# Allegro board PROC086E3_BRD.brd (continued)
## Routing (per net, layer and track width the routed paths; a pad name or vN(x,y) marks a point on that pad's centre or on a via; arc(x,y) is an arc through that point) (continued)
CAPI2S: length 5.3
  TOP w0.178: U2.58 19.15,177.73 18.06,176.64 18.06,175.15 17.88,174.97 C24.1
CAPL12: length 3.3
  TOP w0.178: U2.4 22.58,174.69 v1(22.58,174.68) 22.58,173.73 C26.1
  BOTTOM w0.178: v1(22.58,174.68) 22.58,173.73 C26.1
CAPP12: length 3.8
  TOP w0.178: C23.1 17.56,176.75 19.04,178.23 U2.57
CAPR12: length 3.4
  TOP w0.178: U2.55 18.16,179.23 17.74,178.81 C21.1
CDCE_1V8_I2C_SCL: length 9.8
  TOP w0.178: U9.3 44.81,154.93 44.56,154.68 R68.2 44.56,153.46 43.64,152.54 39.78,152.54 v1(39.17,153.14)
  BOTTOM w0.178: U42.12 39.17,153.25 39.17,153.25 v1(39.17,153.14)
CDCE_1V8_I2C_SDA: length 12.4
  TOP w0.178: U9.4 45.46,154.9 45.72,154.65 R69.2 45.72,153.3 44.58,152.15 39.27,152.15 v1(38.28,153.14)
  BOTTOM w0.178: v1(38.28,153.14) 38.52,153.38 U42.13
CDCE_PCLK: length 21.7
  TOP w0.178: R22.2 R23.1 v1(29.01,169.17)
  BOTTOM w0.178: U42.1 36.86,160.19 36.37,159.7 33.76,159.7 33.3,160.16 33.3,164.37 32.74,164.93 28.32,164.93 27.99,165.26 27.99,168.16 v1(29.01,169.17)
CDCE_S0: length 3.4
  BOTTOM w0.178: R339.2 R342.1 37.89,161.74 38.52,161.11 U42.2
CDCE_VCTR: length 2.4
  TOP w0.178: R54.2 39.56,161.06 v1(39.82,161.32)
  BOTTOM w0.178: U42.4 v1(39.82,161.32)
CDCE_Y1: length 24.4
  TOP w0.178: R27.1 v1(28.5,167.01) ; R63.1 37.52,155.3 v1(37.31,155.51)
  L03_SIG1 w0.107: v1(37.31,155.51) 34.27,155.51 31.07,158.71 27.33,158.71 26.88,159.15 26.88,166.33 27.57,167.01 v1(28.5,167.01)
CMC_FPD_DOUT_N: length 1.5
  TOP w0.102: FL5.2 22.43,161.23 arc(22.83,161.31) C36.2
CMC_FPD_DOUT_P: length 1.5
  TOP w0.102: FL5.1 22.43,160.68 arc(22.83,160.6) C37.2
CMC_FPD_RIN_N: length 1.2
  TOP w0.102: FL3.1 15.62,181.71 arc(15.97,181.64) C17.2
CMC_FPD_RIN_P: length 1.1
  TOP w0.102: FL3.2 15.61,182.26 arc(15.96,182.33) C16.2
CMF: length 3.4
  TOP w0.178: C18.1 17.67,180.24 18.66,181.23 U2.51
CODEC1_ACLKX: length 103.5
  TOP w0.178: v1(65.51,45.96) 65.51,42.25 64.8,41.54 62.15,41.54 61.26,42.43 U32.36 ; U32.7 45.18,45.43 v1(44.68,45.93)
  L03_SIG1 w0.107: v1(44.68,45.93) 47.52,48.78 59.77,48.78 62.59,45.96 v1(65.51,45.96) 66.88,45.96 67.71,46.79 67.71,50.47 66.31,51.88 66.31,70.16 66.06,70.41 65.18,70.41 64.81,70.04 64.81,62.7 64.47,62.36 63.96,62.36 63.6,62.72 63.6,71.84 66.04,74.28 66.04,89.29 v1(65.41,89.91)
  BOTTOM w0.178: R188.2 v1(65.41,89.91)
CODEC1_I2C_ADD0: length 7.5
  TOP w0.178: U32.45 58.99,46.93 59.08,46.85 61.34,46.85 61.85,46.34 61.85,45.12 62.12,44.85 R271.1 R272.2
CODEC1_I2C_ADD1: length 8.2
  TOP w0.178: U32.44 60.99,46.43 61.39,46.03 61.39,44.03 61.74,43.68 R277.1 R278.2
CODEC1_MODE: length 3.6
  TOP w0.178: R264.2 60.62,49.58 R263.2 59.49,48.76 59.17,48.43 U32.48
CODEC1_OVF: length 5.5
  TOP w0.178: TP13.1 U32.5
CODEC1_SCKI: length 25.5
  TOP w0.178: v1(60.78,45.43) 60.28,44.93 U32.41
  BOTTOM w0.178: v1(60.78,45.43) 60.78,46.86 64.58,50.66 64.58,64.12 63.95,64.74 R215.2
CODEC1_VREFAD1: length 12.5
  TOP w0.254: C157.1 45.19,57.01 45.77,56.42 50.37,56.42 51.09,55.7 U32.59
CODEC1_VREFAD2: length 11.5
  TOP w0.254: C161.1 44.54,55.38 45.34,55.38 45.8,55.84 50.09,55.84 50.59,55.33 U32.60
CODEC1_ZERO: length 5.7
  TOP w0.178: TP14.1 41.89,42.43 U32.13
CODEC2_ACLKX: length 44.4
  TOP w0.178: U19.36 v1(45.51,109.39) ; U19.7 v1(59.17,106.39)
  L03_SIG1 w0.107: v1(65.41,98.82) 64.59,99.64 64.59,102.42 63.81,103.2 56.85,103.2 56.61,103.44 56.61,104.15 56.88,104.42 60.72,104.42 60.89,104.6 60.89,104.97 60.59,105.27 56.3,105.27 56.16,105.41 56.16,105.98 56.32,106.13 58.92,106.13 v1(59.17,106.39)
  BOTTOM w0.178: v1(59.17,106.39) 48.51,106.39 v1(45.51,109.39) ; R187.2 v1(65.41,98.82)
CODEC2_I2C_ADD0: length 5.5
  TOP w0.178: U19.45 46.62,104.91 44.3,104.91 43.32,105.89 R167.1 R166.2
CODEC2_I2C_ADD1: length 6.1
  TOP w0.178: U19.44 44.38,105.39 43.64,106.13 43.64,106.76 43.32,107.08 R159.1 R158.2
CODEC2_MODE: length 3.3
  TOP w0.178: R174.2 44.55,102.27 R171.2 U19.48
CODEC2_OVF: length 11.2
  TOP w0.178: v1(68.4,105.78) 67.68,105.06 62.28,105.06 61.52,105.82 60.91,105.82 60.47,105.39 U19.5
CODEC2_SCKI: length 56.3
  TOP w0.178: v1(44.24,107.39) 44.74,106.89 U19.41
  L03_SIG1 w0.107: v1(63.95,74.31) 64.9,75.26 64.9,96.95 66.27,98.32 66.27,101.69 61.09,106.87 58.5,106.87 58.19,106.56 47.14,106.56 46.82,106.89 44.74,106.89 v1(44.24,107.39)
  BOTTOM w0.178: R214.2 v1(63.95,74.31)
CODEC2_VREFAD1: length 8.3
  TOP w0.254: C312.1 51.76,94.62 53.59,96.45 U19.59
CODEC2_VREFAD2: length 7.8
  TOP w0.254: U19.60 54.09,95.73 53.51,95.15 C311.1
CODEC2_ZERO: length 11.2
  TOP w0.178: v1(68.4,111.35) 66.79,109.74 65.28,109.74 64.93,109.39 U19.13
CODEC_RESETN: length 129
  TOP w0.178: U32.4 v1(44.68,46.93) ; v1(61.29,105.27) 60.91,104.89 U19.4 ; U15.1 v1(61.28,133.67)
  L03_SIG1 w0.107: v1(61.29,105.27) 62.2,105.27 65.91,101.56 65.91,98.62 63.88,96.59 63.88,76.12 61.28,73.52 61.28,62.39 55,56.12 41.53,56.12 40.36,54.95 40.36,47.43 40.86,46.93 v1(44.68,46.93)
  L08_SIG2 w0.107: v1(61.29,105.27) 61.3,105.26 64.74,105.26 65.3,105.82 65.3,106.89 70.36,111.95 70.36,119.92 62,128.28 62,132.95 v1(61.28,133.67)
  BOTTOM w0.178: R498.1 v1(44.68,46.93)
CODEC_SCKI: length 51.9
  TOP w0.178: J2.16 v1(93.68,48.63)
  L03_SIG1 w0.107: v1(74.7,70.47) 74.7,48.01 75.05,47.66 92.71,47.66 v1(93.68,48.63)
  BOTTOM w0.178: R538.1 74.68,70.46 v1(74.7,70.47)
CODECA_LIN_L: length 5.7
  BOTTOM w0.381: C332.2 9.86,78.92 J15.5B
CODECA_LIN_L_AC: length 1.1
  BOTTOM w0.381: C332.1 R449.1
CODECA_LIN_R: length 18.5
  BOTTOM w0.381: C134.2 23.82,69.29 22.96,68.44 15.82,68.44 13.39,70.87 9.05,70.87 J15.2B
CODECA_LIN_R_AC: length 1.7
  BOTTOM w0.381: C134.1 R210.1
CODECA_MIC1_L: length 33.2
  TOP w0.381: R227.1 26.26,64.45 23.42,67.29 10.28,67.29 8.48,65.49 J16.5B 8.48,59.45 9.49,58.44 R232.1
CODECA_MIC1_R: length 25.3
  TOP w0.381: R245.1 26.26,50.8 25.99,50.53 16.13,50.53 14.31,52.35 R237.1 9.36,56.46 8.48,55.58 J16.2B
CODECA_MIC2_L: length 23.5
  BOTTOM w0.381: R470.1 11.77,56.46 10.98,55.67 J16.5A 13.19,50.52 25.99,50.52 26.26,50.78 R478.1
CODECA_MIC2_R: length 26.5
  BOTTOM w0.381: R460.1 26.26,64.48 25.52,65.22 J16.2A 10.98,59.23 11.78,58.44 R467.1
CODECA_VOUT1: length 7.9
  BOTTOM w0.381: C373.2 R520.1 11.44,28.35 J19.5B
CODECA_VOUT2: length 7.9
  BOTTOM w0.381: C380.2 R522.1 11.44,24.26 J19.2B
CODECA_VOUT3: length 8
  TOP w0.381: C204.2 R300.1 11.65,24.26 10.98,23.59 J19.5A
CODECA_VOUT4: length 8.1
  TOP w0.381: C196.2 R296.1 11.46,28.35 10.98,28.83 J19.2A
CODECA_VOUT5: length 8
  BOTTOM w0.381: C359.2 R497.1 11.51,44.6 J18.5B
CODECA_VOUT6: length 8
  BOTTOM w0.381: J18.2B 11.51,40.67 R500.1 C366.2
CODECA_VOUT7: length 8.1
  TOP w0.381: J18.5A 10.98,39.84 11.81,40.67 R269.1 C183.2
CODECA_VOUT8: length 8
  TOP w0.381: J18.2A 10.98,45.54 11.92,44.6 R266.1 C168.2
CODECB_LIN_L: length 9.8
  TOP w0.381: C338.2 11.74,76.62 10.98,75.86 J15.5A
CODECB_LIN_L_AC: length 2.4
  TOP w0.381: C338.1 R457.1
CODECB_LIN_R: length 2.3
  BOTTOM w0.381: C122.2 J15.2A
CODECB_LIN_R_AC: length 16.9
  TOP w0.381: R200.1 v1(25.59,76.52)
  BOTTOM w0.381: v1(25.59,76.52) 25.59,80.79 24.83,81.56 C122.1
CODECB_MIC1_L: length 28.3
  TOP w0.381: J13.5B 8.48,92.21 9.33,91.36 R185.1 14.31,95.57 16.26,97.52 25.7,97.52 26.16,97.07 R178.1
CODECB_MIC1_R: length 24.9
  TOP w0.381: R197.1 26.16,84.14 25.82,83.8 16.26,83.8 14.31,85.75 R190.1 9.45,89.38 8.48,88.41 J13.2B
CODECB_MIC2_L: length 23.7
  BOTTOM w0.381: R436.1 26.16,84.13 25.83,83.8 16.26,83.8 14.31,85.75 R430.1 11.87,89.38 10.98,88.5 J13.5A
CODECB_MIC2_R: length 27.1
  BOTTOM w0.381: R419.1 26.16,97.11 25.75,97.52 16.26,97.52 14.31,95.57 R427.1 11.81,91.36 10.98,92.19 J13.2A
CODECB_VOUT1: length 8.1
  BOTTOM w0.381: J12.5B 11.74,109.72 R404.1 C293.2
CODECB_VOUT2: length 8
  BOTTOM w0.381: J12.2B 11.28,105.78 R406.1 C301.2
CODECB_VOUT3: length 7.9
  TOP w0.381: C89.2 R155.1 11.69,105.78 10.98,105.07 J12.5A
CODECB_VOUT4: length 8.4
  TOP w0.381: J12.2A 10.98,110.35 11.61,109.72 R151.1 C72.2
CODECB_VOUT5: length 8
  BOTTOM w0.381: J11.5B 11.51,126.28 R380.1 C279.2
CODECB_VOUT6: length 8
  BOTTOM w0.381: J11.2B 11.51,122.35 R382.1 C286.2
CODECB_VOUT7: length 8.3
  TOP w0.381: J11.5A 10.98,121.9 11.43,122.35 R128.1 C64.2
CODECB_VOUT8: length 8.3
  TOP w0.381: C52.2 R118.1 11.48,126.28 10.98,126.79 J11.2A
CON_UB921_INTB: length 72.6
  TOP w0.178: J1.87 83.01,121.01 v1(82.51,121.51) ; R65.2 v1(33.2,153.42)
  L08_SIG2 w0.107: v1(75.87,121.51) 73.15,124.23 73.15,126.96 70.76,129.35 68.43,129.35 67.16,130.62 67.16,133.05 63.57,136.64 61.37,136.64 60.43,137.58 55.65,137.58 54.69,136.62 52.02,136.62 49.54,139.1 48.25,139.1 45.15,142.2 45.15,146.88 39.88,152.15 34.46,152.15 v1(33.2,153.42)
  BOTTOM w0.178: v1(75.87,121.51) v1(82.51,121.51)
CON_VPFE0_DATA6: length 63.8
  TOP w0.178: U10.13 61.21,139.1 61.49,138.82 62.2,138.82 62.23,138.79 63.5,138.79 64.34,137.96 v1(64.34,137.14) ; J1.22 v1(92.41,99.51)
  L03_SIG1 w0.107: v1(92.41,99.51) 93.25,100.35 93.25,105.75 90.73,108.26 90.73,113.9 83.62,121.01 81.84,121.01 78.28,124.57 78.28,129.8 77.83,130.26 76,130.26 75.89,130.37 75.89,131.01 75.78,131.11 75.57,131.11 75.46,131.01 75.46,130.37 75.36,130.26 70.51,130.26 64.87,135.9 64.87,136.61 v1(64.34,137.14)
CON_VPFE0_DATA7: length 63.6
  TOP w0.178: U10.15 62.21,139.4 62.41,139.2 63.65,139.2 64.85,138.01 64.85,136.66 v1(65.38,136.13) ; J1.24 v1(93.78,100.01)
  L03_SIG1 w0.107: v1(65.38,136.13) 65.38,135.9 67.72,133.56 72.56,133.56 73.33,132.79 78.75,132.79 79.44,132.1 79.44,124.78 82.04,122.18 83.06,122.18 91.14,114.11 91.14,108.57 93.57,106.13 93.57,100.21 v1(93.78,100.01)
CON_VPFE0_DATA11: length 63.6
  TOP w0.178: v1(65.38,137.14) 65.53,137.3 65.53,137.88 63.71,139.7 U10.18 ; J1.56 v1(92.41,108.01)
  L03_SIG1 w0.107: v1(65.38,137.14) 65.9,136.62 65.9,135.83 67.85,133.89 72.67,133.89 73.46,133.1 79.05,133.1 80.52,131.63 80.52,124.32 82.32,122.51 83.76,122.51 84.32,123.07 88.52,123.07 88.82,122.77 89.47,122.77 89.56,122.68 89.56,122.55 89.47,122.45 88.82,122.45 88.72,122.36 88.72,122.23 88.82,122.13 89.47,122.13 89.56,122.04 89.56,121.91 89.47,121.81 88.82,121.81 88.72,121.72 88.72,121.59 88.82,121.49 89.47,121.49 89.56,121.4 89.56,121.27 89.47,121.17 88.82,121.17 88.72,121.08 88.72,120.95 88.82,120.85 89.47,120.85 89.56,120.76 89.56,120.63 89.47,120.53 88.82,120.53 88.72,120.44 88.72,120.31 88.82,120.21 89.47,120.21 89.56,120.12 89.56,119.99 89.47,119.89 88.82,119.89 88.72,119.8 88.72,119.13 91.57,116.29 91.57,108.85 v1(92.41,108.01)
CON_VPFE0_DATA12: length 63.7
  TOP w0.178: v1(93.44,108.01) 92.94,107.51 J1.54 ; U10.21 65.21,139.65 66.42,138.44 v1(66.42,136.13)
  L03_SIG1 w0.107: v1(93.44,108.01) 92.94,108.51 92.94,119.21 92.76,119.39 91.54,119.39 91.39,119.54 91.39,120.9 91.3,121 90.67,121 90.58,121.09 90.58,121.22 90.67,121.32 91.3,121.32 91.39,121.41 91.39,121.54 91.3,121.64 90.67,121.64 90.58,121.73 90.58,121.86 90.67,121.96 91.3,121.96 91.39,122.05 91.39,123.25 91.02,123.62 82.25,123.62 81.2,124.66 81.2,127.67 82.7,129.17 82.7,131.83 81.13,133.41 73.66,133.41 72.87,134.2 68.35,134.2 v1(66.42,136.13)
CONN_HDMI1_CEC: length 12
  TOP w0.178: v1(93.45,181.39) 93.14,181.69 93.14,187.42 v1(90.85,189.71)
  BOTTOM w0.178: U34.7 93.45,181.39 v1(93.45,181.39) ; J4.13 v1(90.85,189.71)
CONN_HDMI1_CLK_N: length 22.7
  BOTTOM w0.102: FL19.3 90.93,175.77 91.04,175.89 91.04,176.26 90.94,176.36 87.65,176.36 87.19,176.83 87.19,180.8 88.82,182.43 88.82,183.47 89.23,183.88 91.58,183.88 91.69,183.98 91.69,184.92 91.5,185.11 U34.15 91.5,186.88 91.71,187.09 91.71,189.04 91.35,189.4 J4.12
CONN_HDMI1_CLK_P: length 22.7
  BOTTOM w0.102: FL19.4 91.48,175.79 91.32,175.95 91.32,176.37 91.06,176.64 87.77,176.64 87.46,176.94 87.46,180.68 89.1,182.32 89.1,183.36 89.35,183.6 91.7,183.6 91.97,183.86 91.97,184.92 92.15,185.11 U34.16 92.15,186.88 91.99,187.04 91.99,189.05 92.35,189.41 J4.10
CONN_HDMI1_HPD: length 15.5
  TOP w0.178: v1(91.82,178.95) 91.82,184.39 87.45,188.76 v1(87.45,189.29)
  BOTTOM w0.178: J4.19 87.85,189.69 v1(87.45,189.29) ; U34.10 91.5,179.27 v1(91.82,178.95)
CONN_HDMI1_SCL: length 18.4
  BOTTOM w0.178: U37.6 78.93,183.33 R319.2 79.17,185.15 81.25,187.23 89.38,187.23 90.07,187.92 D1.1 90.07,188.88 89.85,189.1 J4.15
CONN_HDMI1_SDA: length 18.4
  BOTTOM w0.178: U37.5 78.28,183.39 R320.2 78.09,184.95 80.78,187.64 88.75,187.64 89.13,188.02 D2.1 89.13,188.89 89.35,189.1 J4.16
CONN_HDMI1_TXD0_N: length 23
  BOTTOM w0.102: FL18.3 92.86,175.8 93.01,175.95 93.01,177.08 92.72,177.38 89.17,177.38 88.7,177.85 88.7,180.87 90.18,182.35 92.35,182.35 92.96,182.96 92.96,184.94 92.8,185.11 U34.17 92.8,186.88 92.99,187.06 92.99,188.32 93.21,188.55 93.21,189.02 92.85,189.38 J4.9
CONN_HDMI1_TXD0_P: length 23
  BOTTOM w0.102: J4.7 93.85,189.36 93.49,189 93.49,188.43 93.27,188.2 93.27,187.06 93.45,186.88 U34.18 93.45,185.11 93.24,184.9 93.24,182.85 92.47,182.08 90.3,182.08 88.98,180.75 88.98,177.96 89.28,177.66 92.84,177.66 93.29,177.2 93.29,175.93 93.41,175.81 FL18.4
CONN_HDMI1_TXD1_N: length 22.7
  BOTTOM w0.102: FL17.3 94.79,175.77 94.93,175.91 94.93,177.51 95.3,177.88 98.36,177.88 98.53,178.05 98.53,181.6 98.13,182 95.28,182 94.94,182.34 94.94,183.29 94.67,183.56 94.67,184.09 94.94,184.36 94.94,184.92 94.75,185.11 U34.20 94.75,186.88 94.94,187.06 94.94,188.21 94.71,188.43 94.71,189.17 94.35,189.53 J4.6
CONN_HDMI1_TXD1_P: length 22.7
  BOTTOM w0.102: FL17.4 95.34,175.76 95.21,175.9 95.21,177.39 95.42,177.61 98.48,177.61 98.81,177.94 98.81,181.72 98.25,182.28 95.39,182.28 95.22,182.45 95.22,183.41 94.95,183.68 94.95,183.98 95.22,184.25 95.22,184.92 95.4,185.11 U34.21 95.4,186.88 95.22,187.06 95.22,188.32 94.99,188.55 94.99,189.18 95.35,189.54 J4.4
CONN_HDMI1_TXD2_N: length 22.8
  BOTTOM w0.102: J4.3 95.85,189.43 96.24,189.04 96.24,187.06 96.05,186.88 U34.22 96.05,185.11 96.24,184.92 96.24,183.64 96.56,183.32 99.63,183.32 99.8,183.15 99.8,182.69 100.13,182.36 100.13,182.12 99.8,181.79 99.8,180.84 100.15,180.48 100.15,180.27 99.8,179.91 99.8,178.71 100.1,178.41 100.1,178.14 99.8,177.84 99.8,176.96 99.63,176.79 97.13,176.79 96.87,176.53 96.87,175.87 96.72,175.72 FL16.3
CONN_HDMI1_TXD2_P: length 22.7
  BOTTOM w0.102: J4.1 96.85,189.42 96.52,189.08 96.52,187.06 96.7,186.88 U34.23 96.7,185.11 96.52,184.92 96.52,183.76 96.67,183.6 99.75,183.6 100.08,183.27 100.08,182.8 100.41,182.47 100.41,182 100.08,181.67 100.08,180.95 100.43,180.6 100.43,180.15 100.08,179.79 100.08,178.83 100.38,178.52 100.38,178.03 100.08,177.72 100.08,176.84 99.75,176.51 97.25,176.51 97.15,176.41 97.15,175.89 97.27,175.76 FL16.4
CT_HPD: length 6.2
  TOP w0.178: v1(90.4,178.52) 89.97,178.1 R322.1
  BOTTOM w0.178: v1(90.4,178.52) 90.2,178.72 U34.12
DIR_AUDIO#: length 1.7
  BOTTOM w0.178: Q1.1 U45.1
DIR_BCKO: length 8.8
  TOP w0.178: v1(51.56,140.32) 52.06,139.82 U14.18 U14.17
  BOTTOM w0.178: U45.11 51.35,140.59 51.56,140.38 v1(51.56,140.32)
DIR_BFRAME: length 5.7
  BOTTOM w0.178: U45.18 42.92,140.59 42.67,140.34 39.73,140.34 TP47.1
DIR_CKSEL: length 36.7
  TOP w0.178: v1(44.23,148.66) 44.23,144.95 43.79,144.51 43.79,133.87 45.92,131.73 v1(46.58,131.73) 47.8,130.51 55.85,130.51 56.23,130.13 U15.11
  BOTTOM w0.178: v1(44.23,148.66) R351.2 R352.1 R355.2 42.98,147.27 43.16,147.09 U45.28
DIR_CLKST: length 6.9
  BOTTOM w0.178: TP48.1 48.46,141.4 48.96,141.89 U45.9
DIR_COUT: length 2.1
  BOTTOM w0.178: U45.15 TP50.1
DIR_DOUT: length 7.6
  TOP w0.178: v1(49.09,139.94) 50.11,138.92 U14.21
  BOTTOM w0.178: U45.12 v1(49.09,139.94)
DIR_EMPH: length 10.2
  BOTTOM w0.178: Q3.1 U45.17
DIR_ERROR: length 5.5
  BOTTOM w0.178: U45.27 42.49,146.44 42,146.93 R355.1 Q2.1
DIR_FILT: length 10.5
  TOP w0.178: R101.1 41.45,136.04 41.83,136.43 C277.1 41.83,142.4 v1(42.23,142.79)
  BOTTOM w0.178: U45.22 42.63,143.19 v1(42.23,142.79)
DIR_FMT0: length 43.2
  TOP w0.178: R97.2 v1(40.89,145.97) 38.82,145.97 36.03,143.18 36.03,136.49 40.89,131.63 45.44,131.63 47.02,130.06 55.7,130.06 56.12,129.63 U15.12
  BOTTOM w0.178: U45.25 41.72,145.14 v1(40.89,145.97) R360.1
DIR_FMT1: length 46.1
  TOP w0.178: R96.2 v1(40.84,147.11) 39.26,147.11 35.65,143.51 35.65,136.09 40.51,131.22 45.29,131.22 46.94,129.57 55.6,129.57 56.29,128.88 U15.13
  BOTTOM w0.178: U45.26 42.16,145.79 v1(40.84,147.11) R357.1
DIR_JACK: length 9.3
  TOP w0.178: J8.2 23.04,141.66 23.32,141.38 R102.1 C47.2
DIR_JACK_AC: length 3.7
  TOP w0.178: C47.1 25.55,136.03 U13.1 24.31,137.19 24.13,137.37 R100.2
DIR_LRCKO: length 11.5
  TOP w0.178: U14.14 U14.15 54.01,139.71 v1(51.82,141.91)
  BOTTOM w0.178: v1(51.82,141.91) 51.16,141.24 U45.10
DIR_PSCK0: length 20
  TOP w0.178: U15.14 v1(59.28,128.1)
  BOTTOM w0.178: v1(59.28,128.1) 58.08,129.29 53.52,129.29 52.55,130.26 52.55,135.29 52.88,135.62 R365.2 R363.1 52.88,138.9 52.48,139.29 U45.13
DIR_PSCK1: length 20.5
  TOP w0.178: v1(59.28,127.08) 59.78,127.58 U15.15
  BOTTOM w0.178: U45.14 51.56,138.64 51.79,138.41 R364.1 R366.2 51.79,135.59 52.12,135.26 52.12,130.08 53.34,128.86 57.49,128.86 v1(59.28,127.08)
DIR_RESETN: length 26.1
  TOP w0.178: U15.10 56.32,130.63 56.06,130.89 48.69,130.89 v1(47.9,131.68) 47.09,132.49 45.72,132.49 44.42,133.79 R98.2 v1(45.65,142.54)
  BOTTOM w0.178: R98.2 v1(45.65,142.54)
DIR_RSV: length 2.4
  BOTTOM w0.178: U45.19 42.84,141.24 42.58,140.99 R361.1
DIR_RXIN: length 15.3
  BOTTOM w0.178: U45.20 SW1.2
DIR_RXIN_COAX: length 2.2
  TOP w0.178: SW1.1 U13.4
DIR_SCKO: length 12.6
  TOP w0.178: v1(51.35,145.14) 50.76,144.56 U14.20
  BOTTOM w0.178: U45.4 v1(51.35,145.14)
DIR_UOUT: length 4.5
  BOTTOM w0.178: U45.16 45.98,139.29 46.33,138.95 TP49.1
DIR_XTI: length 12.4
  BOTTOM w0.178: Y1.1 C276.1 55.58,141.38 54.42,142.54 U45.8
DIR_XTO: length 7
  BOTTOM w0.178: R359.1 55.58,144.31 54.46,143.19 U45.7
DIT_GND: length 14.3
  TOP w0.381: R116.2 J9.1 68.48,128.61 68.48,135.15 J9.3
DIT_JACK: length 4.2
  TOP w0.178: R104.2 J9.2
DIT_JACK_AC: length 2.3
  TOP w0.178: R119.2 R112.1 C51.1
EEPROM_A0: length 9
  TOP w0.178: J2.19 82.37,49.63 82.23,49.77 79.12,49.77 78.88,49.53 R251.2 U30.1
EEPROM_A1: length 9.2
  TOP w0.178: U30.2 R249.2 78.9,50.8 79.08,50.97 81.72,50.97 82.57,50.13 J2.21
EEPROM_A2: length 9.8
  TOP w0.178: J2.23 82.96,50.63 81.15,52.43 79.18,52.43 78.89,52.14 R246.2 U30.3
EEPROM_WP: length 21.5
  TOP w0.178: J2.25 83.09,51.13 81.34,52.88 79.69,52.88 78.74,53.83 70.42,53.83 69.93,53.34 R248.2 U30.7
EXP_3V3: length 2
  TOP w0.254: J2.6 90.71,46.13 90.64,46.06
  TOP w0.305: J2.6 92.16,46.13 92.46,45.83
EXP_DC_3V3: length 10.9
  BOTTOM w0.381: J17.60 83.55,53.37 v1(83.44,53.26) 83.27,53.09 R475.2 ; J17.59 v1(93.64,53.37) ; R473.2 83.3,54.28 v1(83.44,54.15) 83.46,54.17 J17.58 ; J17.57 v1(93.64,54.17)
EXP_I2C1_SCL: length 4.1
  TOP w0.178: R218.2 v1(82.95,69.16)
  BOTTOM w0.178: J17.30 83.16,69.37 v1(82.95,69.16)
EXP_I2C1_SDA: length 4.1
  TOP w0.178: R216.2 v1(82.95,70.38)
  BOTTOM w0.178: J17.28 83.16,70.17 v1(82.95,70.38)
EXP_I2C2_SCL: length 2.4
  TOP w0.178: R310.2 v1(64.13,18.11)
  BOTTOM w0.178: J20.22 v1(64.13,18.11)
EXP_I2C2_SDA: length 2.4
  TOP w0.178: R298.2 v1(64.13,26.86)
  BOTTOM w0.178: J20.21 v1(64.13,26.86)
EXP_I2C4_SCL: length 2.5
  BOTTOM w0.178: J14.11 R434.2
EXP_I2C4_SDA: length 2.5
  BOTTOM w0.178: J14.12 R446.2
EXP_REFCLK: length 4.1
  TOP w0.178: TP11.1 95.01,50.13 J2.22
EXP_RSTZ: length 2.2
  TOP w0.178: J1.118 v1(92.41,128.51)
  BOTTOM w0.178: J1.118 v1(92.41,128.51)
FPD_DE: length 80.4
  TOP w0.178: U8.5 30.94,166.27 v1(31.44,166.77) ; U10.7 58.21,142.1 57.53,142.78 54.28,142.78 53.83,143.23 53.83,143.77 54.09,144.03 59.1,144.03 59.28,144.2 59.28,144.46 58.57,145.16 54.39,145.16 53.83,145.72 53.83,151.53 51.94,153.42 v1(51.94,154.85)
  L03_SIG1 w0.107: v1(51.94,154.85) 51.46,154.36 45.95,154.36 43.92,156.4 34.34,156.4 32.69,158.05 32.69,165.52 31.95,166.26 31.95,167.19 30.83,168.31 30.83,169.44 30.72,169.55 30.51,169.55 30.4,169.44 30.4,168.97 30.3,168.87 30.08,168.87 29.98,168.97 29.98,169.87 30.08,169.97 30.63,169.97 30.73,170.08 30.73,170.39 30.63,170.49 29.92,170.49 29.08,169.65 27.25,169.65 27.03,169.43 27.03,169.21 27.13,169.1 27.77,169.1 27.88,168.99 27.88,168.18 27.77,168.07 27.56,168.07 27.45,168.18 27.45,168.57 27.35,168.67 27.13,168.67 27.03,168.57 27.03,167.85 27.38,167.5 30.72,167.5 v1(31.44,166.77)
FPD_DOUT_N: length 17.1
  TOP w0.102: J7.3 6.44,165.22 arc(6.71,165.4) 7.03,165.46 7.47,165.46 arc(8.01,165.36) 8.46,165.05 9.63,163.89 arc(9.72,163.81) 9.82,163.74 arc(9.86,163.71) 9.91,163.69 arc(9.92,163.68) 9.93,163.68 arc(9.97,163.66) 10.02,163.64 arc(10.19,163.6) 10.36,163.58 15.54,163.58 arc(16.67,163.36) 17.63,162.72 19.05,161.3 arc(19.28,161.15) 19.56,161.09 20.22,161.09 arc(20.4,161.13) FL5.3
FPD_DOUT_P: length 17
  TOP w0.102: J7.1 7.5,161.25 arc(7.52,161.12) 7.59,161.02 arc(7.71,160.94) 7.84,160.92 9.01,160.92 arc(9.11,160.94) 9.19,160.99 arc(9.23,161.05) 9.25,161.12 9.25,162.23 arc(9.32,162.61) 9.54,162.94 9.72,163.11 arc(9.93,163.26) 10.18,163.3 15.54,163.3 arc(16.56,163.1) 17.43,162.52 18.85,161.11 arc(19.17,160.89) 19.56,160.81 20.22,160.81 arc(20.4,160.78) FL5.4
FPD_HSYNC: length 80.5
  TOP w0.178: U10.5 57.21,142.01 56.92,142.3 53.95,142.3 53.42,142.83 53.42,151.36 50.95,153.83 v1(50.95,154.85) ; v1(32.44,166.77) 31.94,166.27 U8.3
  L03_SIG1 w0.107: v1(32.44,166.77) 32.44,167.61 32.26,167.8 31.85,167.8 31.14,168.51 31.14,169.96 31.25,170.07 31.46,170.07 31.57,169.96 31.57,168.77 31.67,168.66 31.89,168.66 31.99,168.77 31.99,170.39 31.89,170.49 31.34,170.49 31.14,170.7 31.14,172.53 31.34,172.72 32.04,172.72 32.15,172.62 32.15,171.98 32.26,171.87 33.57,171.87 33.68,171.98 33.68,172.19 33.57,172.3 32.68,172.3 32.58,172.4 32.58,172.62 32.68,172.72 34.16,172.72 35.1,171.79 35.1,170.82 33.63,169.36 33.48,169.36 33.33,169.51 33.33,169.66 34.56,170.89 34.56,171.05 34.41,171.2 34.26,171.2 33.65,170.59 33.5,170.59 33.35,170.74 33.35,170.89 33.6,171.14 33.6,171.29 33.45,171.44 33.3,171.44 32.75,170.89 32.75,170.74 33.2,170.29 33.2,170.14 32.72,169.66 32.72,169.51 33.18,169.05 33.18,168.9 33.02,168.75 33.02,158.3 34.59,156.73 44.2,156.73 45.54,155.38 50.42,155.38 v1(50.95,154.85)
FPD_PCLK: length 77.7
  TOP w0.178: U10.28 68.71,142.19 66.83,144.08 61.16,144.08 59.28,145.96 55.07,145.96 54.66,146.36 54.66,152.46 v1(53.37,153.75) ; v1(28.24,170.14) 25.91,170.14 25.73,169.96 25.73,168.37 25.91,168.19 R22.1 R26.1
  L03_SIG1 w0.107: v1(53.37,153.75) 53.37,154.34 51.99,155.71 45.75,155.71 44.4,157.06 34.77,157.06 33.35,158.48 33.35,168.64 35.41,170.7 35.41,171.92 34.29,173.03 31.92,173.03 31.62,173.34 30.35,173.34 28.24,171.23 v1(28.24,170.14)
FPD_RIN_N: length 11.4
  TOP w0.102: J5.2 5.5,181.57 6.18,180.9 arc(6.28,180.83) 6.4,180.8 8.3,180.8 arc(8.75,180.99) 8.94,181.44 8.94,181.89 arc(9.36,182.91) 10.38,183.33 10.62,183.33 arc(10.88,183.27) 11.1,183.12 11.91,182.31 arc(12.44,181.96) 13.06,181.84 13.64,181.84 arc(13.82,181.81) FL3.4
FPD_RIN_P: length 11.3
  TOP w0.102: J5.4 6.56,184.7 6.56,185.2 arc(6.67,185.47) 6.94,185.58 8.35,185.58 arc(8.76,185.41) 8.94,184.99 8.94,184.36 arc(9.16,183.83) 9.69,183.6 10.62,183.6 arc(10.99,183.53) 11.3,183.32 12.11,182.51 arc(12.54,182.22) 13.06,182.12 13.64,182.12 arc(13.82,182.16) FL3.3
FPD_VSYNC: length 80.5
  TOP w0.178: v1(52.7,154.29) 52.7,153.35 54.25,151.81 54.25,146.19 54.9,145.54 58.73,145.54 60.81,143.47 60.81,143.11 59.74,142.05 59.74,140.71 U10.10 ; U8.4 v1(31.44,165.75)
  L03_SIG1 w0.107: v1(31.44,165.75) 31.44,166.13 31.29,166.28 30.72,166.28 30.61,166.17 30.61,165.72 30.5,165.62 30.29,165.62 30.18,165.72 30.18,166.17 30.08,166.28 28.26,166.28 28.16,166.17 28.16,165.51 28.05,165.41 27.84,165.41 27.73,165.51 27.73,166.17 27.62,166.28 27.39,166.28 27.23,166.12 27.23,165.29 27.34,165.18 31.88,165.18 32.11,164.96 32.11,164.14 31.9,163.94 31.39,163.94 31.28,164.05 31.28,164.39 31.17,164.5 30.96,164.5 30.85,164.39 30.85,164.05 30.75,163.94 30.53,163.94 30.42,164.05 30.42,164.65 30.31,164.76 30.1,164.76 29.99,164.65 29.99,164.05 29.89,163.94 29.67,163.94 29.57,164.05 29.57,164.65 29.46,164.76 29.25,164.76 29.14,164.65 29.14,164.05 29.03,163.94 28.82,163.94 28.71,164.05 28.71,164.65 28.61,164.76 28.39,164.76 28.29,164.65 28.29,164.05 28.18,163.94 27.97,163.94 27.86,164.05 27.86,164.65 27.75,164.76 27.34,164.76 27.23,164.65 27.23,163.33 27.58,162.97 28.3,162.97 28.62,162.66 28.62,162.08 28.5,161.96 27.53,161.96 27.23,161.65 27.23,160.23 27.58,159.88 31.44,159.88 31.67,159.65 31.67,158.58 34.19,156.07 43.79,156.07 45.85,154.01 52.43,154.01 v1(52.7,154.29)
FSOUT0: length 4.9
  BOTTOM w0.178: U45.2 48.58,146.44 48.01,147.02 48.01,149.08 TP42.1
FSOUT1: length 6.9
  BOTTOM w0.178: TP43.1 46.1,147.07 47.38,145.79 U45.3
GPIO0_31: length 50.4
  TOP w0.178: U4.13 v1(44.1,166.89) ; U11.31 v1(83.28,147.03)
  L03_SIG1 w0.107: v1(83.28,147.03) 81.75,148.55 79.5,148.55 79.04,149 71.02,149 70.87,148.85 67.44,148.85 65.33,150.96 65.33,152.05 55.83,161.55 49.59,161.55 44.25,166.89 v1(44.1,166.89)
GPIO0_32: length 58.5
  TOP w0.178: U3.12 U3.11 v1(38.49,166.89) ; U11.29 v1(84.28,147.03)
  L03_SIG1 w0.107: v1(84.28,147.03) 83.79,146.54 83.03,146.54 81.38,148.19 79.4,148.19 78.94,148.65 71.17,148.65 71.02,148.5 66.19,148.5 64.99,149.7 64.99,151.89 55.68,161.2 49.51,161.2 44.3,166.41 38.97,166.41 v1(38.49,166.89)
HDMI1_CEC: length 6.5
  TOP w0.178: v1(97.35,179.09) 99.99,176.45 v1(99.99,175.73)
  BOTTOM w0.178: U34.1 v1(97.35,179.09) ; TP25.1 v1(99.99,175.73)
HDMI1_CLK_N: length 8
  BOTTOM w0.102: FL19.2 90.93,173.87 91.06,173.74 91.06,173.54 90.93,173.41 88.67,173.41 88.15,172.89 88.15,169.84 88.04,169.73 U41.21
HDMI1_CLK_P: length 8
  BOTTOM w0.102: U41.22 88.54,169.73 88.43,169.84 88.43,172.77 88.79,173.13 91.05,173.13 91.34,173.43 91.34,173.74 91.48,173.89 FL19.1
HDMI1_CTL1: length 7.2
  TOP w0.178: R49.1 v1(78.7,161.72)
  BOTTOM w0.178: R49.1 v1(78.7,161.72) 81.11,161.72 82.27,162.87 U41.8
HDMI1_CTL2: length 5.2
  TOP w0.178: R52.1 v1(80.86,160.85)
  BOTTOM w0.178: R52.1 v1(80.86,160.85) 82.39,162.37 U41.7
HDMI1_CTL3: length 8
  TOP w0.178: v1(78.74,159.67) 78.42,159.99 R53.1
  BOTTOM w0.178: R53.1 78.42,159.99 v1(78.74,159.67) 78.89,159.52 80.26,159.52 82.62,161.87 U41.6
HDMI1_DATA0: length 26
  BOTTOM w0.178: R72.2 71.73,148.61 71.73,152.66 71.98,152.92 73.96,152.92 75.49,154.44 75.49,156.67 75.9,157.08 78.23,157.08 78.42,156.89 78.42,156.32 78.58,156.17 78.83,156.17 79.04,156.37 79.04,156.82 79.19,156.98 79.41,156.98 79.57,156.82 79.57,156.37 79.78,156.17 84.68,156.17 84.84,156.32 84.84,156.62 85,156.78 85.22,156.78 85.37,156.62 85.37,156.32 85.53,156.17 86.36,156.17 86.54,156.35 U41.63
HDMI1_DATA0_R: length 1.8
  TOP w0.178: U11.54 v1(71.78,147.03)
  BOTTOM w0.178: v1(71.78,147.03) 71.78,147.03 R72.1
HDMI1_DATA1: length 25.8
  BOTTOM w0.178: R73.2 72.68,148.56 72.29,148.95 72.29,149.23 72.44,149.39 73.22,149.39 73.38,149.55 73.38,149.84 73.2,150.02 72.31,150.02 72.14,150.2 72.14,151.22 72.81,151.89 72.81,152.33 72.98,152.51 74.27,152.51 75.9,154.13 75.9,156.52 76.05,156.68 77.85,156.68 78.03,156.5 78.03,155.96 78.21,155.79 86.74,155.79 87.04,156.08 U41.62
HDMI1_DATA1_R: length 1.8
  TOP w0.178: U11.52 v1(72.78,147.03)
  BOTTOM w0.178: R73.1 72.75,147.06 v1(72.78,147.03)
HDMI1_DATA2: length 26.2
  BOTTOM w0.178: R74.2 74.28,148.56 74.46,148.74 74.46,148.99 74.28,149.17 73.91,149.17 73.76,149.32 73.76,150.32 73.61,150.48 72.7,150.48 72.52,150.66 72.52,150.94 72.68,151.09 73.05,151.09 73.2,151.25 73.2,151.87 73.38,152.05 75.26,152.05 75.44,152.23 75.44,153.12 76.3,153.98 76.3,156.09 76.48,156.27 77.47,156.27 77.62,156.12 77.62,155.58 77.8,155.41 86.92,155.41 87.54,156.02 U41.61
HDMI1_DATA2_R: length 1.8
  TOP w0.178: U11.50 v1(73.78,147.02)
  BOTTOM w0.178: v1(73.78,147.02) 73.76,147.04 R74.1
HDMI1_DATA3: length 26
  BOTTOM w0.178: U41.60 88.04,155.96 87.1,155.02 77.39,155.02 77.22,155.2 77.22,155.74 77.06,155.89 76.81,155.89 76.68,155.76 76.68,153.11 76.53,152.96 76.15,152.96 76,152.8 76,152.48 76.15,152.32 76.53,152.32 76.68,152.17 76.68,151.85 76.5,151.67 73.74,151.67 73.61,151.54 73.61,151.04 74.47,150.17 75.06,150.17 75.23,150 R75.2
HDMI1_DATA3_R: length 1.8
  TOP w0.178: U11.47 v1(75.28,147.03)
  BOTTOM w0.178: R75.1 75.23,147.07 v1(75.28,147.03)
HDMI1_DATA4: length 23.2
  BOTTOM w0.178: U41.59 88.54,155.91 87.27,154.64 77.24,154.64 77.06,154.47 77.06,153.83 77.32,153.58 77.72,153.58 78.03,153.27 78.03,152.81 77.72,152.51 77.27,152.51 77.06,152.31 77.06,151.65 76.71,151.29 75.23,151.29 75.11,151.17 75.11,150.68 75.21,150.58 75.56,150.58 75.74,150.4 75.74,149.07 R76.2
HDMI1_DATA4_R: length 4.5
  TOP w0.178: U11.45 76.28,147 75.78,146.5 v1(75.78,145.88)
  BOTTOM w0.178: R76.1 76.18,147.65 76.18,146.29 v1(75.78,145.88)
HDMI1_DATA5: length 26
  BOTTOM w0.178: R77.2 77.27,148.9 77.09,149.08 76.33,149.08 76.2,149.21 76.2,149.46 76.35,149.61 77.27,149.61 77.42,149.77 77.42,150.06 77.26,150.22 76.31,150.22 76.15,150.38 76.15,150.71 76.33,150.88 77.29,150.88 77.47,151.06 77.47,151.7 78.44,152.66 78.44,153.42 78.28,153.58 78.28,154.08 78.46,154.26 79.03,154.26 79.19,154.11 79.19,152.82 79.34,152.66 79.78,152.66 79.96,152.84 79.96,154.11 80.12,154.26 87.45,154.26 89.04,155.85 U41.58
HDMI1_DATA5_R: length 1.8
  TOP w0.178: U11.43 v1(77.28,147.03)
  BOTTOM w0.178: R77.1 77.27,147.04 v1(77.28,147.03)
HDMI1_DATA6: length 23.2
  BOTTOM w0.178: U41.55 90.54,153.84 90.14,153.45 89.89,153.45 89.74,153.61 89.74,154.18 89.58,154.34 89.29,154.34 89.14,154.18 89.14,153.61 88.98,153.45 88.75,153.45 88.6,153.6 88.6,153.81 88.42,153.98 88.29,153.98 87.76,153.45 81.33,153.45 80.16,152.28 78.61,152.28 77.88,151.54 77.88,150.13 78.03,149.97 78.33,149.97 78.49,149.82 78.49,149.6 78.33,149.44 78.03,149.44 77.88,149.29 77.88,148.97 R78.2
HDMI1_DATA6_R: length 4.6
  TOP w0.178: v1(77.75,145.89) 77.78,145.89 78.28,146.38 U11.41
  BOTTOM w0.178: v1(77.75,145.89) 77.85,145.99 77.85,147.29 R78.1
HDMI1_DATA7: length 23.2
  BOTTOM w0.178: R79.2 78.89,148.97 78.89,150.2 78.71,150.38 78.46,150.38 78.28,150.55 78.28,151.39 78.79,151.9 79.11,151.9 79.26,151.74 79.26,150.69 79.42,150.53 79.64,150.53 79.8,150.69 79.8,151.74 79.95,151.9 80.33,151.9 81.5,153.07 90.32,153.07 91.04,153.78 U41.54
HDMI1_DATA7_R: length 4.5
  TOP w0.178: U11.39 79.28,146.38 v1(78.78,145.88)
  BOTTOM w0.178: R79.1 79.3,146.41 v1(78.78,145.88)
HDMI1_DATA8: length 23.4
  BOTTOM w0.178: U41.53 91.54,153.72 90.47,152.66 84.27,152.66 84.11,152.51 84.11,152.01 83.95,151.85 83.73,151.85 83.58,152.01 83.58,152.51 83.42,152.66 81.64,152.66 81.33,152.36 81.33,151.4 81.17,151.24 80.47,151.24 80.31,151.09 80.31,150.87 80.47,150.71 81.17,150.71 81.33,150.56 81.33,150.33 81.17,150.18 80.32,150.18 80.16,150.02 80.16,149.8 80.32,149.64 81.17,149.64 81.33,149.49 81.33,149.11 80.84,148.61 R80.2
HDMI1_DATA8_R: length 4.6
  TOP w0.178: v1(80.28,145.88) 80.78,146.38 U11.36
  BOTTOM w0.178: v1(80.28,145.88) 80.83,146.44 80.83,147.71 R80.1
HDMI1_DATA9: length 26
  BOTTOM w0.178: R81.2 81.79,149.13 81.94,149.29 82.44,149.29 82.6,149.45 82.6,149.67 82.44,149.82 82,149.82 81.84,149.98 81.84,152.05 82.04,152.26 82.83,152.26 83.04,152.05 83.04,149.72 83.2,149.56 83.51,149.56 83.67,149.72 83.67,150.68 83.82,150.83 84.04,150.83 84.2,150.68 84.2,149.72 84.36,149.56 84.61,149.56 84.79,149.74 84.79,151.34 84.94,151.49 89.87,151.49 92.04,153.67 U41.52
HDMI1_DATA9_R: length 1.9
  TOP w0.178: U11.34 v1(81.78,147.03)
  BOTTOM w0.178: v1(81.78,147.03) 81.79,147.04 R81.1
HDMI1_DATA10: length 23.4
  BOTTOM w0.178: U41.51 92.54,153.61 90.02,151.09 85.65,151.09 85.19,150.63 85.19,148.88 85.88,148.19 85.88,145.91 85.74,145.78 85.37,145.78 85.19,145.96 85.19,148.14 84.18,149.16 83.35,149.16 R82.2
HDMI1_DATA10_R: length 4.6
  TOP w0.178: v1(83.28,145.88) 82.78,146.38 U11.32
  BOTTOM w0.178: R82.1 82.75,147.72 82.75,146.41 v1(83.28,145.88)
HDMI1_DATA11: length 23.1
  BOTTOM w0.178: R83.2 84.16,148.61 84.8,147.97 84.8,145.59 85,145.4 85.9,145.4 86.26,145.75 86.26,148.39 85.57,149.08 85.57,150.45 85.8,150.68 86.55,150.68 86.81,150.43 89.92,150.43 93.04,153.55 U41.50
HDMI1_DATA11_R: length 4.6
  TOP w0.178: v1(84.28,145.88) 83.78,146.38 U11.30
  BOTTOM w0.178: v1(84.28,145.88) 83.78,146.38 83.78,147.73 R83.1
HDMI1_DATA12: length 25.9
  BOTTOM w0.178: R84.2 86.87,148.93 86.87,149.84 87.05,150.02 87.37,150.02 87.53,149.86 87.53,149.36 87.68,149.21 87.9,149.21 88.06,149.36 88.06,149.86 88.22,150.02 90.07,150.02 93.78,153.73 93.78,154.75 94.63,155.6 94.63,157.07 94.78,157.23 96.82,157.23 96.98,157.39 96.98,157.61 96.82,157.76 94.63,157.76 94.48,157.92 94.48,158.33 94.65,158.5 96.8,158.5 96.98,158.68 96.98,159.7 96.8,159.87 U41.47
HDMI1_DATA12_R: length 1.8
  TOP w0.178: U12.54 v1(87.22,147.03)
  BOTTOM w0.178: R84.1 v1(87.22,147.03)
HDMI1_DATA13: length 22.9
  BOTTOM w0.178: U41.46 97.18,160.37 97.36,160.2 97.36,156.73 97.2,156.57 95.51,156.57 95.35,156.42 95.35,156.2 95.51,156.04 97.2,156.04 97.36,155.88 97.36,155.53 97.18,155.35 94.95,155.35 94.18,154.59 94.18,153.58 89.76,149.16 88.8,149.16 R85.2
HDMI1_DATA13_R: length 5
  TOP w0.178: U12.52 88.22,146.88 v1(87.22,145.88)
  BOTTOM w0.178: v1(87.22,145.88) 87.88,146.55 87.88,147.38 88.22,147.71 R85.1
HDMI1_DATA14: length 23.2
  BOTTOM w0.178: R86.2 89.4,148.4 89.92,148.4 90.07,148.55 90.07,148.9 92.15,150.99 93.27,150.99 94.59,152.31 94.59,154.44 95.1,154.95 95.5,154.95 95.61,154.85 95.61,153.68 95.76,153.53 96.16,153.53 96.37,153.73 96.37,154.77 96.55,154.95 97.56,154.95 97.74,155.13 97.74,160.66 97.53,160.87 U41.45
HDMI1_DATA14_R: length 4.5
  TOP w0.178: v1(88.72,145.88) 89.22,146.38 U12.50
  BOTTOM w0.178: v1(88.72,145.88) 89.22,146.38 R86.1
HDMI1_DATA15: length 25.2
  BOTTOM w0.178: R87.2 90.72,148.99 92.3,150.58 93.42,150.58 95,152.15 95,152.89 95.17,153.07 95.91,153.07 96.07,152.91 96.07,152.16 96.22,152 96.6,152 96.77,152.18 96.77,154.37 96.95,154.55 97.26,154.55 97.43,154.37 97.43,153.25 97.61,153.07 97.97,153.07 98.15,153.25 98.15,161.12 97.89,161.37 U41.44
HDMI1_DATA15_R: length 2.4
  TOP w0.178: v1(90.37,146.87) 90.72,147.22 U12.47
  BOTTOM w0.178: R87.1 90.72,147.22 v1(90.37,146.87)
HDMI1_DATA16: length 23.4
  BOTTOM w0.178: U41.43 98.23,161.87 98.53,161.58 98.53,151.77 98.35,151.6 98.03,151.6 97.88,151.75 97.88,152.51 97.72,152.66 97.4,152.66 97.24,152.51 97.24,151.75 97.08,151.6 95,151.6 93.57,150.17 92.48,150.17 91.72,149.41 R88.2
HDMI1_DATA16_R: length 4.5
  TOP w0.178: v1(91.22,145.88) 91.72,146.38 U12.45
  BOTTOM w0.178: R88.1 91.72,146.38 v1(91.22,145.88)
HDMI1_DATA17: length 23.2
  BOTTOM w0.178: R89.2 92.72,149.52 92.91,149.72 93.22,149.72 93.34,149.59 93.34,149.34 93.52,149.16 93.73,149.16 94.28,149.72 94.28,150.33 95.15,151.19 98.76,151.19 98.93,151.37 98.93,162.09 98.65,162.37 U41.42
HDMI1_DATA17_R: length 4.5
  TOP w0.178: U12.43 92.72,146.38 v1(92.22,145.88)
  BOTTOM w0.178: v1(92.22,145.88) 92.72,146.38 R89.1
HDMI1_DATA18: length 23.2
  BOTTOM w0.178: U41.41 98.98,162.87 99.31,162.54 99.31,150.96 99.14,150.78 96.12,150.78 95.96,150.63 95.96,150.12 95.76,149.92 95.5,149.92 95.34,150.08 95.34,150.17 95.19,150.33 94.87,150.33 94.69,150.15 94.69,149.55 R90.2
HDMI1_DATA18_R: length 4.5
  TOP w0.178: v1(93.22,145.88) 93.72,146.38 U12.41
  BOTTOM w0.178: v1(93.22,145.88) 93.72,146.38 R90.1
HDMI1_DATA19: length 23.1
  BOTTOM w0.178: U41.40 99.47,163.37 99.75,163.1 99.75,150.55 99.57,150.38 96.88,150.38 95.66,149.16 95.66,148.67 95.48,148.5 94.8,148.5 R91.2
HDMI1_DATA19_R: length 4.5
  TOP w0.178: v1(94.22,145.88) 94.22,146.25 94.72,146.75 U12.39
  BOTTOM w0.178: v1(94.22,145.88) 94.22,146.22 94.72,146.72 R91.1
HDMI1_DATA20: length 23
  BOTTOM w0.178: R92.2 96.22,149.16 97.03,149.97 99.95,149.97 100.13,150.15 100.13,163.49 99.75,163.87 U41.39
HDMI1_DATA20_R: length 4.5
  TOP w0.178: v1(95.72,145.88) 96.22,146.38 U12.36
  BOTTOM w0.178: R92.1 96.22,146.38 v1(95.72,145.88)
HDMI1_DATA21: length 23.2
  BOTTOM w0.178: U41.38 100.07,164.37 100.53,163.91 100.53,149.8 100.3,149.57 98.21,149.57 R93.2
HDMI1_DATA21_R: length 4.5
  TOP w0.178: U12.34 97.22,146.38 v1(96.72,145.88)
  BOTTOM w0.178: v1(96.72,145.88) 96.72,146.31 97.22,146.81 R93.1
HDMI1_DATA22: length 24.8
  BOTTOM w0.178: U41.37 100.74,164.87 101.04,164.57 101.04,148.98 100.86,148.8 100.01,148.8 99.63,149.18 98.42,149.18 98.22,148.98 R94.2
HDMI1_DATA22_R: length 3.1
  TOP w0.178: v1(98.55,146.52) 98.22,146.85 U12.32
  BOTTOM w0.178: R94.1 98.22,146.85 v1(98.55,146.52)
HDMI1_DATA23: length 25.9
  BOTTOM w0.178: U41.36 100.89,165.37 101.47,164.79 101.47,148.17 101.04,147.73 100.06,147.73 99.87,147.92 99.87,148.4 99.69,148.58 R95.2
HDMI1_DATA23_R: length 1.8
  TOP w0.178: U12.30 v1(99.22,147.03)
  BOTTOM w0.178: R95.1 v1(99.22,147.03)
HDMI1_DE: length 30.4
  TOP w0.178: v1(82.42,159.06) 82.02,159.47 79.6,159.47 78.38,158.25 64.9,158.25 58.57,151.93 R61.2
  BOTTOM w0.178: v1(82.42,159.06) 83.23,159.87 U41.2
HDMI1_DE_R: length 1.8
  TOP w0.178: R61.1 58.21,149.44 U10.50
HDMI1_DKEN: length 2.8
  TOP w0.178: R29.2 96.74,166 v1(96.62,165.87)
  BOTTOM w0.178: U41.35 v1(96.62,165.87) 96.74,166 R29.2
HDMI1_HSYNC: length 31.6
  TOP w0.178: R60.2 57.61,151.54 64.82,158.76 v1(77.32,158.76)
  BOTTOM w0.178: U41.4 82.79,160.87 80.37,158.45 80.36,158.45 80.29,158.38 78.99,158.38 78.61,158.76 v1(77.32,158.76)
HDMI1_HSYNC_R: length 1.8
  TOP w0.178: U10.52 57.21,149.41 R60.1
HDMI1_ISEL: length 7.9
  TOP w0.178: R32.2 v1(77.55,165.37)
  BOTTOM w0.178: R32.2 v1(77.55,165.37) C251.1 U41.13
HDMI1_PCLK: length 24.8
  TOP w0.178: v1(80.62,153.48) 80.47,153.63 70.66,153.63 69.9,152.87 v1(69.9,151.75)
  BOTTOM w0.178: U41.57 TP40.1 88.9,155.15 87.58,153.83 80.98,153.83 v1(80.62,153.48) ; R67.2 v1(69.9,151.75)
HDMI1_PCLK_R: length 3
  TOP w0.178: v1(68.78,149.61) 68.21,149.04 U10.30
  BOTTOM w0.178: v1(68.78,149.61) 69.3,149.61 R67.1
HDMI1_TXD0_N: length 8
  BOTTOM w0.102: FL18.2 92.86,173.92 93,173.79 93,173.41 91.98,172.4 90.11,172.4 89.65,171.94 89.65,169.84 89.54,169.73 U41.24
HDMI1_TXD0_P: length 8
  BOTTOM w0.102: FL18.1 93.41,173.94 93.27,173.8 93.27,173.29 92.1,172.12 90.22,172.12 89.93,171.82 89.93,169.84 90.04,169.73 U41.25
HDMI1_TXD1_N: length 8
  BOTTOM w0.102: FL17.2 94.79,173.9 94.93,173.76 94.93,173.13 94.73,172.93 94.12,172.93 92.52,171.33 91.48,171.33 91.15,171 91.15,169.84 91.04,169.73 U41.27
HDMI1_TXD1_P: length 8
  BOTTOM w0.102: U41.28 91.54,169.73 91.43,169.84 91.43,170.89 91.59,171.05 92.63,171.05 94.23,172.65 94.84,172.65 95.21,173.01 95.21,173.73 95.34,173.86 FL17.1
HDMI1_TXD2_N: length 8.1
  BOTTOM w0.102: 96.72,174.23 96.72,173.9 96.86,173.76 96.86,172.94 94.28,170.37 92.91,170.37 92.65,170.1 92.65,169.85 92.54,169.73 U41.30
HDMI1_TXD2_P: length 8.1
  BOTTOM w0.102: U41.31 93.04,169.73 92.93,169.84 92.93,169.99 93.03,170.09 94.4,170.09 97.14,172.82 97.14,173.75 97.27,173.89 97.27,174.23
HDMI1_VSYNC: length 29.6
  TOP w0.178: v1(80.06,158.96) 78.94,157.84 73.15,157.84 70.97,155.66 62.98,155.66 60.25,152.93 R57.2
  BOTTOM w0.178: U41.5 82.68,161.37 80.26,158.96 v1(80.06,158.96)
HDMI1_VSYNC_R: length 1.8
  TOP w0.178: R57.1 59.71,149.27 U10.47
HDMI_BSEL: length 6.7
  TOP w0.178: R25.1 v1(78.96,167.07)
  BOTTOM w0.178: U41.15 81.82,166.37 81.12,167.07 v1(78.96,167.07) R25.1
HDMI_DDC_OE: length 50.9
  TOP w0.178: R328.1 v1(94.75,179.04)
  L03_SIG1 w0.107: v1(94.75,179.04) 93.44,177.73 v1(84.43,177.73) 82.38,175.69 80.38,175.69 76.56,171.86 v1(75.44,171.86)
  BOTTOM w0.178: U34.5 v1(94.75,179.04) ; v1(75.44,171.86) 74.16,170.59 74.16,161.04 73.22,160.1 68.4,160.1 67.75,159.45 U43.11 ; v1(84.43,177.73) 84.43,179.66 82,182.1 U37.8
HDMI_DSEL: length 4.4
  TOP w0.178: R28.1 v1(81.12,166.14)
  BOTTOM w0.178: R28.1 v1(81.12,166.14) 81.38,165.87 U41.14
HDMI_EDGE: length 4.9
  TOP w0.178: R48.1 v1(80.86,162.58)
  BOTTOM w0.178: U41.9 81.66,163.37 v1(80.86,162.58) R48.1
HDMI_HPD: length 43.7
  L03_SIG1 w0.107: v1(75.44,170.99) 76.12,170.99 80.42,175.29 91.9,175.29 95.48,178.88 v1(95.76,178.88)
  BOTTOM w0.178: v1(95.76,178.88) 95.4,179.23 U34.4 ; U43.12 68.25,159.24 68.61,159.6 73.43,159.6 74.68,160.84 74.68,170.23 v1(75.44,170.99)
HDMI_PDN: length 24.1
  TOP w0.178: v1(66.75,160.57) 73.69,160.57 75.72,162.59 78.03,162.59 78.84,163.41 v1(80.19,163.41)
  BOTTOM w0.178: U43.10 67.25,160.07 v1(66.75,160.57) TP117.1 ; U41.10 81.44,163.87 80.98,163.41 v1(80.19,163.41) 78.84,163.41 78.55,163.12 R340.2
HDMI_TFADJ: length 2.8
  TOP w0.178: R21.2 87.02,170.15 v1(87.04,170.17)
  BOTTOM w0.178: U41.19 v1(87.04,170.17)
HDMI_VREF: length 4.5
  BOTTOM w0.178: U41.3 82.84,160.37 80.81,158.34 R346.1
I2C0_SCL: length 4.3
  TOP w0.178: v1(82.73,125.56) 83.21,125.56 84.16,126.51 J1.109
  BOTTOM w0.178: v1(82.73,125.56) 82.07,125.56 81.89,125.38 TP55.1
I2C0_SDA: length 6.9
  TOP w0.178: J1.111 84.08,127.01 83.39,126.32 v1(82.75,126.32)
  BOTTOM w0.178: TP56.1 79.83,125.97 80.19,126.32 v1(82.75,126.32)
I2C1_SCL: length 140.6
  TOP w0.178: R50.2 v1(44.55,162.83) ; v1(74.5,155.05) 84.45,155.05 85.19,154.31 85.19,137.3 83.01,135.11 83.01,127.92 83.47,127.46 83.72,127.46 v1(83.77,127.51) J1.113 ; U8.8 v1(29.44,165.75)
  L08_SIG2 w0.107: v1(74.5,155.05) 74.04,155.51 74.04,168.83 77.62,172.41 77.62,174.63 78.28,175.29 v1(78.28,176.36) 75.67,176.36 75.31,176 71.4,176 70.56,176.84 47.6,176.84 46.46,175.7 46.46,174.94 46.75,174.64 46.75,165.04 v1(44.55,162.83)
  BOTTOM w0.178: U37.3 78.93,177.01 v1(78.28,176.36) ; R376.2 83.44,127.19 83.76,127.51 v1(83.77,127.51) ; U43.19 68.53,153.88 73.33,153.88 v1(74.5,155.05) ; v1(29.44,165.75) 31.09,167.39 36.27,167.39 37.64,166.02 42.67,166.02 43.59,165.11 43.59,163.8 v1(44.55,162.83)
I2C1_SDA: length 143.8
  TOP w0.178: R51.2 45.72,163.82 45.47,164.07 v1(44.58,164.07) ; v1(74.55,156.12) 74.88,155.79 84.56,155.79 85.57,154.77 85.57,137.09 83.52,135.04 83.52,128.63 v1(83.72,128.43) 84.14,128.01 J1.115 ; U8.9 28.94,166.27 v1(29.44,166.77)
  L08_SIG2 w0.107: v1(74.55,156.12) 74.55,168.89 78.94,173.29 78.94,176.71 v1(78.28,177.37) 75.02,177.37 74.68,177.02 70.99,177.02 70.74,177.27 47.57,177.27 46.08,175.78 46.08,174.81 46.44,174.44 46.44,165.93 v1(44.58,164.07)
  BOTTOM w0.178: v1(29.44,166.77) 30.47,167.8 39.32,167.8 40.64,166.48 42.85,166.48 44.58,164.75 v1(44.58,164.07) ; v1(83.72,128.43) 83.62,128.33 R374.2 ; U37.4 v1(78.28,177.37) ; U43.20 67.75,153.59 68,153.35 73.58,153.35 75.01,154.77 75.01,155.66 v1(74.55,156.12)
I2C3_SCL: length 256.5
  TOP w0.178: v1(94.71,47.13) 94.21,46.63 J2.8 ; v1(63.88,129.84) 63.68,129.63 U15.19 ; U19.42 v1(45.51,106.39) ; v1(21.84,174.71) 22.08,174.95 U2.3 ; U32.42 v1(59.51,45.43)
  L03_SIG1 w0.107: v1(60.13,90.49) 60.13,95.4 64.26,99.54 64.26,102.22 63.67,102.81 48.26,102.81 45.51,105.55 v1(45.51,106.39)
  L08_SIG2 w0.107: v1(45.51,106.39) 45.51,105.61 47.76,103.36 57.32,103.36 58.36,104.4 65.05,104.4 68.96,108.31 68.96,109.47 71.04,111.55 71.04,120.15 63.88,127.31 v1(63.88,129.84) 64.14,130.09 64.14,133.43 60.3,137.27 55.78,137.27 54.82,136.31 51.89,136.31 49.41,138.79 48.12,138.79 44.84,142.07 44.84,146.7 39.73,151.81 32.46,151.81 30.18,154.09 30.18,157.34 29.82,157.69 27.46,157.69 23.83,161.32 23.83,164.19 21.42,166.6 21.42,174.28 v1(21.84,174.71) ; v1(94.71,47.13) 93.26,45.67 67.34,45.67 66.59,44.92 60.03,44.92 v1(59.51,45.43) 59.51,46.26 60.44,47.19 60.44,69.39 58.75,71.08 58.75,89.12 v1(60.13,90.49)
  BOTTOM w0.178: R434.1 v1(60.13,90.49) ; R491.1 v1(94.71,47.13)
I2C3_SDA: length 256.9
  TOP w0.178: U32.43 v1(60.15,45.93) ; U2.2 21.58,175.18 v1(21.11,174.71) ; U19.43 44.74,105.89 v1(44.24,106.39) ; J2.10 v1(93.68,47.13) ; U15.20 v1(62.81,130.13)
  L03_SIG1 w0.107: v1(60.13,76.4) 60.13,79.61 59.63,80.11 59.63,95.41 63.91,99.69 63.91,102.04 63.45,102.5 48.13,102.5 v1(44.24,106.39)
  L08_SIG2 w0.107: v1(60.13,76.4) 59.63,75.9 59.63,70.68 60.75,69.56 60.75,47.02 60.15,46.41 v1(60.15,45.93) 61.09,45.93 61.75,45.27 66.34,45.27 67.06,45.98 92.53,45.98 v1(93.68,47.13) ; v1(44.24,106.39) 44.74,106.88 45.82,106.88 46.29,106.41 46.29,105.27 47.89,103.67 57.19,103.67 58.25,104.73 64.74,104.73 65.63,105.62 65.63,106.76 70.71,111.84 70.71,120.02 62.81,127.92 v1(62.81,130.13) 63.1,130.13 63.75,130.79 63.75,133.36 61.11,136 51.77,136 49.29,138.48 48,138.48 44.53,141.94 44.53,146.57 39.6,151.5 29,151.5 26.75,153.75 26.75,157.96 23.52,161.19 23.52,163.01 21.11,165.43 v1(21.11,174.71)
  BOTTOM w0.178: v1(93.68,47.13) 94.82,48.27 R485.1 ; R446.1 v1(60.13,76.4)
I2C6_SCL: length 155.3
  TOP w0.178: J2.107 83.98,76.63 v1(83.72,76.37) R208.2
  L03_SIG1 w0.107: v1(93.73,83.04) 93.73,81.71 91.83,79.82 87.16,79.82 v1(83.72,76.37)
  L08_SIG2 w0.107: v1(93.73,83.04) 95.15,84.46 95.15,95.92 96.72,97.49 96.72,140.03 96.22,140.53 96.22,147.49 95.49,148.22 94.39,148.22 83.82,158.78 83.82,166.23 81.52,168.52 81.52,176.83 80.31,178.04 72.77,178.04 71.82,178.99 62.42,178.99 61.62,179.79 58.37,179.79 57.57,178.99 47.82,178.99 v1(47.75,178.93)
  BOTTOM w0.178: v1(47.75,178.93) 47.32,178.93 47.13,179.12 U36.6
I2C6_SDA: length 155.1
  TOP w0.178: R206.2 v1(83.72,77.39) 83.98,77.13 J2.109
  L03_SIG1 w0.107: v1(92.9,81.83) 91.34,80.27 86.6,80.27 v1(83.72,77.39)
  L08_SIG2 w0.107: v1(47.78,179.71) 48.18,179.31 57.38,179.31 58.22,180.15 61.82,180.15 62.66,179.31 72.26,179.31 72.52,179.05 79.93,179.05 81.83,177.16 81.83,168.65 84.13,166.35 84.13,159 94.6,148.53 96.21,148.53 97.22,147.52 97.22,140.25 97.73,139.74 97.73,138.94 97.1,138.31 97.1,97.42 96.32,96.63 96.32,84.72 93.43,81.83 v1(92.9,81.83)
  BOTTOM w0.178: U36.5 47.78,179.77 47.78,179.76 v1(47.78,179.71)
I2S_CLK: length 2.7
  TOP w0.178: R18.2 19.24,175.07 20.04,175.88 U2.1
IDCK#: length 2.3
  TOP w0.178: R58.1 v1(90.04,156.29)
  BOTTOM w0.178: R58.1 v1(90.04,156.29)
IO_EXP_RESETN: length 79.7
  TOP w0.178: U15.24 62.56,132.13 v1(62.93,132.51) ; v1(92.47,113.36) R146.1 R144.1
  BOTTOM w0.178: U43.24 65.75,153.64 65.02,152.92 64.06,152.92 62.67,151.53 62.67,142.24 61.34,140.9 61.34,136.04 62.67,134.7 62.67,132.76 v1(62.93,132.51) 62.9,132.51 62.03,131.63 62.03,127.5 64.58,124.95 75.31,124.95 77.8,122.46 85.55,122.46 86.89,123.81 93.98,123.81 94.67,123.12 94.67,114.03 93.99,113.36 v1(92.47,113.36)
JAMR3_GPIO0: length 22.7
  TOP w0.178: J1.17 83.49,98.51 75.23,90.25 v1(70.43,90.25)
  BOTTOM w0.178: J14.33 68.93,88.75 v1(70.43,90.25)
JAMR3_GPIO1: length 30.3
  TOP w0.178: v1(69.6,77.5) 70.44,78.35 70.44,84.36 82.59,96.51 J1.9
  BOTTOM w0.178: J14.34 68.93,78.17 v1(69.6,77.5)
JAMR3_GPIO2: length 44.5
  TOP w0.178: J1.89 83.23,121.51 82.56,122.18 82.13,122.18 81.9,121.95 v1(81.9,117.6)
  L08_SIG2 w0.107: v1(81.9,117.6) 80.81,116.51 80.81,106.89 v1(81.09,106.61)
  BOTTOM w0.178: J14.35 69.73,88.35 78.09,96.72 78.09,103.61 v1(81.09,106.61)
JAMR3_I2S_CLK: length 165.8
  TOP w0.178: U10.45 60.71,147.37 61.85,146.24 v1(65.33,146.24)
  L08_SIG2 w0.107: v1(65.33,146.24) 66.89,147.8 70.32,147.8 70.68,148.16 85.39,148.16 87.12,146.43 87.41,146.43 89.1,144.74 90.37,144.74 93.22,141.89 93.22,141.59 93.52,141.28 93.83,141.28 94.89,140.22 94.89,131.58 96.37,130.11 96.37,97.62 92.38,93.63 92.38,60.28 96.44,56.22 96.44,35.21 93.29,32.06 84.24,32.06 v1(83.74,32.57)
  BOTTOM w0.178: v1(83.74,32.57) 84.54,31.77 J17.104
JAMR3_I2S_DA: length 147.6
  TOP w0.178: v1(66.57,146.24) 66.21,146.6 U10.34
  L08_SIG2 w0.107: v1(66.57,146.24) 67.06,145.75 69.34,145.75 71.1,147.51 84.45,147.51 88.58,143.38 89.4,143.38 89.79,142.99 89.79,142.58 92.2,140.17 92.2,133.36 95.72,129.84 95.72,97.89 91.73,93.9 91.73,60.01 95.8,55.95 95.8,35.76 v1(93.85,33.82)
  BOTTOM w0.178: J17.103 93.53,31.77 93.85,32.09 v1(93.85,33.82)
JAMR3_I2S_DB: length 103
  TOP w0.178: v1(94.69,124.32) 93.37,124.32 93.06,124.01 J1.100
  L08_SIG2 w0.107: v1(94.69,124.32) 95.38,123.63 95.38,107.73 91.36,103.72 91.36,59.83 95.4,55.79 95.4,40.5 v1(94.51,39.61)
  BOTTOM w0.178: J17.105 93.95,30.97 94.51,31.53 v1(94.51,39.61)
JAMR3_I2S_WC: length 155.3
  TOP w0.178: U10.32 67.21,146.89 v1(67.87,146.24)
  L08_SIG2 w0.107: v1(84.75,32.57) 93.32,32.57 96.11,35.37 96.11,56.09 92.05,60.16 92.05,93.76 96.04,97.75 96.04,129.98 93.22,132.8 93.22,141.13 90.12,144.23 88.19,144.23 84.59,147.83 70.86,147.83 69.27,146.24 v1(67.87,146.24)
  BOTTOM w0.178: J17.102 v1(84.75,32.57)
JAMR3_PWR_CTRL: length 109.7
  TOP w0.178: U15.3 60.28,134.37 60.45,134.55 66.95,134.55 67.43,134.07 67.43,125.47 68.52,124.38 72.14,124.38 76.38,120.14 76.38,111.29 68.63,103.54 68.63,56.78 71.2,54.21 79.63,54.21 v1(80.33,53.51)
  BOTTOM w0.178: R475.1 80.75,53.09 v1(80.33,53.51)
JAMR3_RESETN: length 130.3
  TOP w0.178: U15.2 60.78,133.99 60.95,134.17 66.62,134.17 66.93,133.87 66.93,125.33 68.39,123.87 71.88,123.87 75.84,119.91 75.84,111.36 68,103.51 68,51.93 67.44,51.37 67.44,48.85 68,48.29 68,33.93 v1(60.93,26.86) R297.1
  BOTTOM w0.178: J20.13 v1(60.93,26.86) 60.91,26.89 TP103.1
LI_CAM_RST#: length 22.3
  TOP w0.178: v1(55.45,180.07) 55.57,180.19 R11.1 ; v1(49.73,179.81) 47.22,177.3 41.33,177.3 38.89,174.87 U3.5
  BOTTOM w0.178: R11.1 55.57,180.19 v1(55.45,180.07) 54.89,179.51 50.04,179.51 v1(49.73,179.81)
LI_CAM_TRIGGER: length 16.1
  TOP w0.178: R10.2 v1(54.57,180.05) 52.74,180.05 48.44,175.75 44.7,175.75 44.1,175.15 U4.4
  BOTTOM w0.178: R10.2 v1(54.57,180.05)
LI_SPI3_CLK: length 23.4
  TOP w0.178: v1(54.99,186.23) 54.98,186.22 52.76,186.22 50.29,183.75 50.29,179.59 47.6,176.89 44.15,176.89 42.9,175.65 U4.7
  BOTTOM w0.178: J6.32 56.07,185.15 v1(54.99,186.23)
LI_SPI3_CS0: length 21.5
  TOP w0.178: v1(55.07,185.11) 54.42,185.76 52.93,185.76 50.72,183.55 50.72,179.36 47.88,176.51 44.33,176.51 43.3,175.48 U4.6
  BOTTOM w0.178: J6.34 v1(55.07,185.11)
LI_SPI3_MISO: length 12.6
  TOP w0.178: v1(51.92,178.52) 51.92,178.49 48.52,175.09 U5.5
  BOTTOM w0.178: J6.31 56.57,179.84 55.85,179.13 52.53,179.13 v1(51.92,178.52)
LI_SPI3_MOSI: length 18.8
  TOP w0.178: U4.5 43.7,175.32 44.52,176.13 48.11,176.13 51.26,179.28 51.26,182.3 v1(54.07,185.11)
  BOTTOM w0.178: J6.36 v1(54.07,185.11)
LI_VIN_DATA0: length 23.8
  TOP w0.178: v1(58.07,185.11) 58.07,183.73 57.91,183.57 57.56,183.57 57.4,183.42 57.4,183.2 57.56,183.04 57.91,183.04 58.07,182.88 58.07,182.66 57.91,182.51 57.56,182.51 57.4,182.35 57.4,182.13 57.56,181.97 57.91,181.97 58.07,181.82 58.07,181.6 57.91,181.44 57.56,181.44 57.4,181.28 57.4,181.06 57.56,180.91 57.91,180.91 58.07,180.75 58.07,179.69 57.89,179.51 52.78,179.51 52.54,179.27 52.54,175.99 52.39,175.84 50.91,175.84 50.75,175.68 50.75,175.46 50.91,175.3 52.39,175.3 52.54,175.15 U6.47
  BOTTOM w0.178: J6.28 v1(58.07,185.11)
LI_VIN_DATA1: length 23.8
  TOP w0.178: U6.46 52.94,178.83 53.24,179.13 58.41,179.13 v1(58.57,179.29)
  BOTTOM w0.178: v1(58.57,179.29) 58.57,178.27 58.39,178.09 54.01,178.09 53.83,178.27 53.83,178.52 54.01,178.7 57.78,178.7 57.96,178.88 57.96,179.69 58.57,180.29 J6.27
